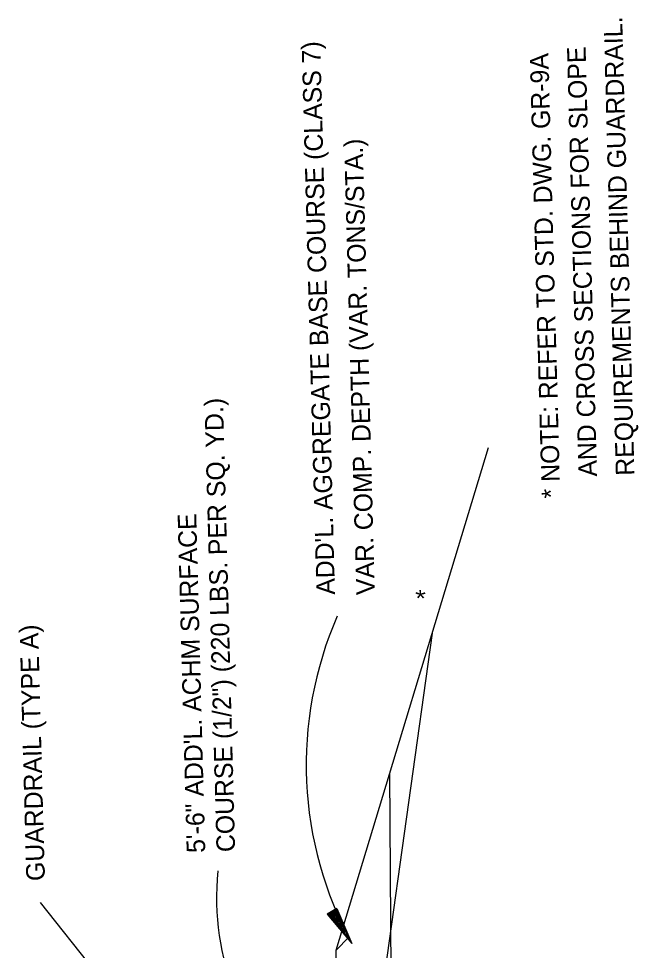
# Model space of a CAD drawing. Extents: x 1929624 to 1936506, y 596315 to 605721.
# Drawn here: x 1931811.5 to 1932011.6, y 600751.8 to 601052.9 of the extents above; entities that cross this region are included whole.
import ezdxf

# ---------------------------------------------------------------- set-up
doc = ezdxf.new("R2010")
doc.units = 0
doc.layers.add('Default', color=7, linetype='Continuous')

msp = doc.modelspace()

# ---------------------------------------------------------------- linework, layer by layer
at = {"layer": 'Default'}
for p, q in [((1931914.06, 600751.77), (1931963.27, 600914.26)), ((1931912.31, 600618.68), (1931945.12, 600854.29)), ((1931934.09, 600420.4), (1931931.39, 600809)), ((1931872.05, 600700.18), (1931818.5, 600767.22)), ((1931914.28, 600765.34), (1931911.15, 600763.41)), ((1931913.51, 600764.83), (1931915.85, 600759.23)), ((1931913.75, 600764.99), (1931916.92, 600757.51)), ((1931914.02, 600765.16), (1931918.04, 600755.74)), ((1931914.28, 600765.34), (1931919.08, 600754)), ((1931911.15, 600763.41), (1931919.08, 600754)), ((1931911.43, 600763.59), (1931918.04, 600755.74)), ((1931911.7, 600763.74), (1931916.92, 600757.51)), ((1931911.94, 600763.89), (1931915.85, 600759.23)), ((1931912.22, 600764.05), (1931914.78, 600760.98)), ((1931912.49, 600764.22), (1931913.72, 600762.75)), ((1931912.96, 600764.53), (1931913.72, 600762.75)), ((1931913.25, 600764.68), (1931914.78, 600760.98)), ((1931914.06, 600751.77), (1931918.1, 600756.06)), ((1931912.31, 600618.68), (1931914.06, 600751.77))]:
    msp.add_line(p, q, dxfattribs=at)
msp.add_arc((1932024.57, 600811.67), 120.21, 156.4253, 208.6755, dxfattribs=at)
msp.add_ellipse((1931915.32, 600773.75), major_axis=(-5.72, -60.23), ratio=0.655798, start_param=4.712389, end_param=6.093533, dxfattribs=at)

# ---------------------------------------------------------------- texts
for s, rotation, p in [('   REQUIREMENTS BEHIND GUARDRAIL.', 91.5377, (1932010.57, 600898.59)), ("ADD'L. AGGREGATE BASE COURSE (CLASS 7)", 91.5377, (1931913.68, 600866.77)), ('* NOTE: REFER TO STD. DWG. GR-9A', 91.5377, (1931986.43, 600897.94)), ('   AND CROSS SECTIONS FOR SLOPE', 91.5377, (1931998.5, 600898.27)), ('VAR. COMP. DEPTH (VAR. TONS/STA.)', 91.5377, (1931926.55, 600866.71)), ('COURSE (1/2") (220 LBS. PER SQ. YD.)', 91.5377, (1931881.42, 600783.6)), ('5\'-6" ADD\'L. ACHM SURFACE ', 91.5377, (1931871.78, 600783.34)), ('*', 73.189, (1931945.05, 600864.08)), ('GUARDRAIL (TYPE A)', 91.5377, (1931819.99, 600774.26))]:
    msp.add_text(s, height=6, rotation=rotation, dxfattribs=at).set_placement(p)

doc.saveas('drawing.dxf')
